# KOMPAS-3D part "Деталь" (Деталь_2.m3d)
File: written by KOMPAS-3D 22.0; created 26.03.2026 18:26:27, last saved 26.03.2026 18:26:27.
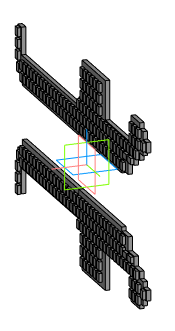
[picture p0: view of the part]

Document properties: Автор: Пользователь Windows; Полное имя файла: F:\Танк\Деталь_2.m3d

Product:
- Part/product: Деталь

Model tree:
1. Операция без истории:1
2. Операция без истории:2
3. Операция без истории:3
4. Операция без истории:4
